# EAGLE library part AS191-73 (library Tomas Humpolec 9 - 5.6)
PHEMT GaAs IC High Linearity 3 V Control SPDT Switch 0.1?2 GHz Alpha Features +2.5 to +5 V Linear Operation Harmonics H2, H3 > 65 dBc PIN = 34.5 dBm Low Insertion Loss (0.5 dB 0.9 GHz) High Isolation (27 dB @ 0.9 GHz) Ultra Miniature SOT-6 Package PHEMT Process Description The AS191-73 is a PHEMT GaAs FET IC high linearity SPDT switch in a SOT-6 plastic package. This switch has been designed for use where extremely high linearity, low control voltage, high isolation, low insertion loss and ultra miniature package size are required. It can be controlled with positive, negative or a combination of both voltages. Some standard implementations include antenna changeover, T/R and diversity switching over 3 W. The AS191-73 switch can be used in many analog and digital wireless communication systems including cellular, GSM and DECT applications.
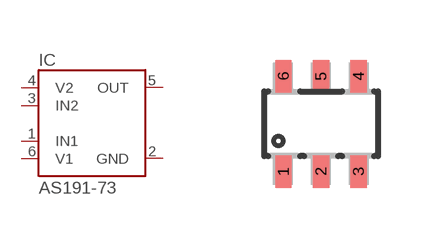
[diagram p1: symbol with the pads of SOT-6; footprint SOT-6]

Designator prefix IC

## AS191-73  [SOT-6]
1  IN1  in
2  GND  pwr
3  IN2  in
4  V2
5  OUT  out
6  V1

## Footprint SOT-6 (pad centres in mm)
SMD - SOT-6
smd 0.406 x 0.813: 1 -0.94,-1.194; 2 0,-1.194; 3 0.94,-1.194; 4 0.94,1.194; 5 0,1.194; 6 -0.94,1.194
